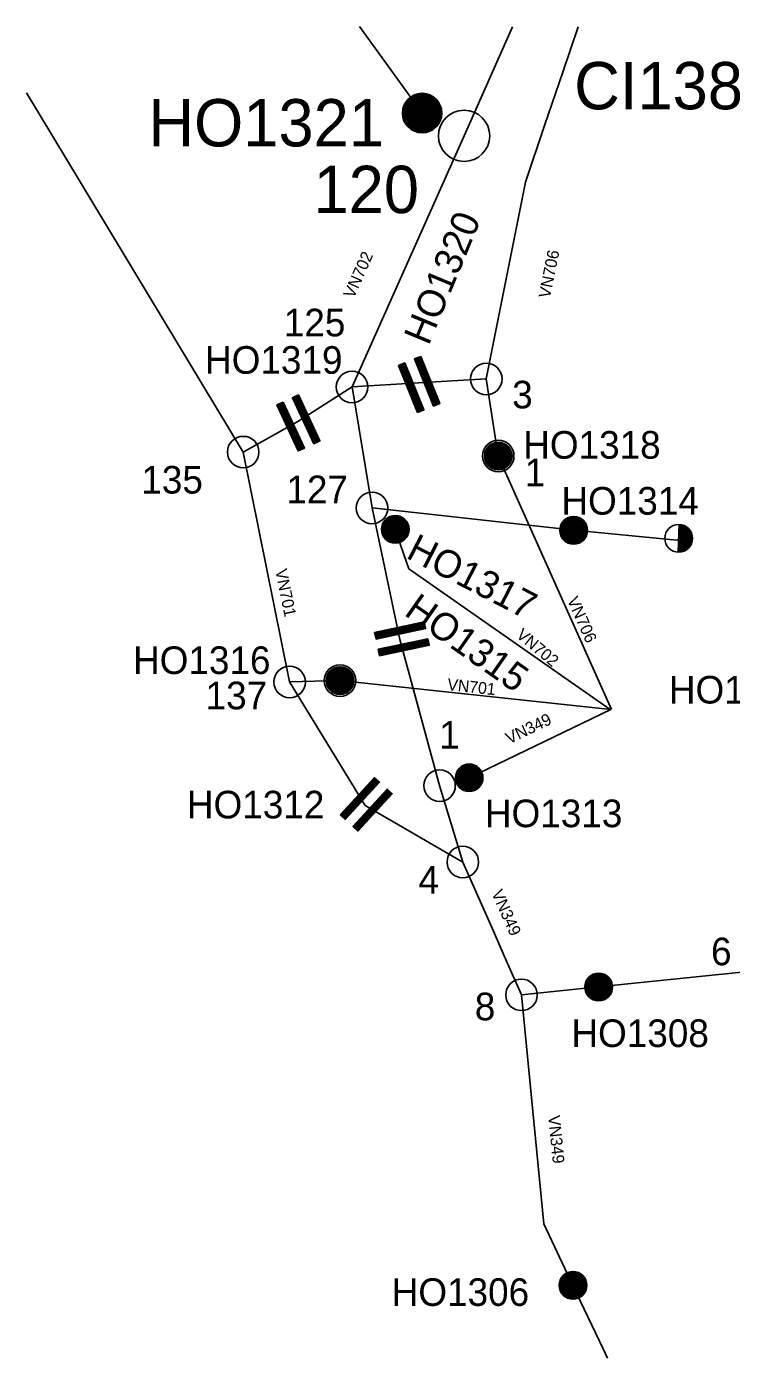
# Model space of a CAD drawing. Extents: x -536823 to -534989, y -1202231 to -1200421.
# Drawn here: x -536823 to -535929, y -1202141 to -1200454 of the extents above; entities that cross this region are included whole.
import ezdxf

# ---------------------------------------------------------------- set-up
doc = ezdxf.new("R2010")
doc.units = 0
for name, color, linetype in [('Default', 7, 'Continuous'), ('Vrstva 1', 7, 'Continuous'), ('Vrstva 2', 7, 'Continuous'), ('Vrstva 3', 7, 'Continuous'), ('Vrstva 5', 7, 'Continuous')]:
    doc.layers.add(name, color=color, linetype=linetype)

# ---------------------------------------------------------------- blocks, each defined once
blk = doc.blocks.new('PS100')
at = {"layer": 'Default'}
for p, q in [((-17.5, -0.7), (0.7, 17.5)), ((-17.5, 0.7), (-0.7, 17.5)), ((-17.4, -2), (2, 17.4)), ((-17.3, 2.2), (-2.2, 17.3)), ((-17.2, -3.3), (3.3, 17.2)), ((-17, 4), (-4, 17)), ((-16.9, -4.4), (4.4, 16.9)), ((-16.6, -5.5), (5.5, 16.6)), ((-16.4, 6), (-6, 16.4)), ((-16.2, -6.5), (6.5, 16.2)), ((-15.8, -7.5), (7.5, 15.8)), ((-15.3, -8.4), (8.4, 15.3)), ((-15.2, 8.6), (-8.6, 15.2)), ((-14.8, -9.3), (9.3, 14.8)), ((-14.2, -10.2), (10.2, 14.2)), ((-13.6, -11), (11, 13.6)), ((-13, -11.7), (11.7, 13)), ((-12.3, -12.5), (12.5, 12.3)), ((-11.5, -13.2), (13.2, 11.5)), ((-10.8, -13.8), (13.8, 10.8)), ((-9.9, -14.4), (14.4, 9.9)), ((-9.1, -14.9), (14.9, 9.1)), ((-8.2, -15.5), (15.5, 8.2)), ((-7.2, -15.9), (15.9, 7.2)), ((-6.2, -16.3), (16.3, 6.2)), ((-5.2, -16.7), (16.7, 5.2)), ((-4.1, -17), (17, 4.1)), ((-2.9, -17.2), (17.2, 2.9)), ((-1.6, -17.4), (17.4, 1.6)), ((-0.3, -17.5), (17.5, 0.3)), ((1.1, -17.4), (17.4, -1.1)), ((2.7, -17.3), (17.3, -2.7)), ((4.5, -16.9), (16.9, -4.5)), ((6.7, -16.2), (16.2, -6.7)), ((9.7, -14.5), (14.5, -9.7))]:
    blk.add_line(p, q, dxfattribs=at)
blk.add_circle((0, 0), 17.5, dxfattribs=at)
blk = doc.blocks.new('PS110')
at = {"layer": 'Default'}
for p, q in [((-15.1, 21.8), (-7.6, 29.3)), ((-15.1, 23.2), (-9.1, 29.3)), ((-15.1, 24.6), (-10.5, 29.3)), ((-15.1, 26), (-11.9, 29.3)), ((-15.1, 27.4), (-13.3, 29.3)), ((-15.1, 28.8), (-14.7, 29.3)), ((-15.1, 20.4), (-6.6, 28.9)), ((-15.1, 18.9), (-6.6, 27.5)), ((-15.1, 17.5), (-6.6, 26.1)), ((-15.1, 16.1), (-6.6, 24.7)), ((-15.1, 14.7), (-6.6, 23.3)), ((-15.1, 13.3), (-6.6, 21.8)), ((-15.1, 11.9), (-6.6, 20.4)), ((-15.1, 10.5), (-6.6, 19)), ((-15.1, 9), (-6.6, 17.6)), ((-6.6, -35), (-6.6, 29.3)), ((6.6, 20.7), (15.2, 29.3)), ((6.6, 22.1), (13.7, 29.3)), ((6.6, 23.5), (12.3, 29.3)), ((6.6, 24.9), (10.9, 29.3)), ((6.6, 26.4), (9.5, 29.3)), ((6.6, 27.8), (8.1, 29.3)), ((6.6, 29.2), (6.7, 29.3)), ((6.6, 19.3), (15.2, 27.8)), ((6.6, 17.9), (15.2, 26.4)), ((6.6, 16.5), (15.2, 25)), ((6.6, 15), (15.2, 23.6)), ((6.6, 13.6), (15.2, 22.2)), ((6.6, 12.2), (15.2, 20.8)), ((6.6, 10.8), (15.2, 19.4)), ((6.6, 9.4), (15.2, 18)), ((-15.1, 7.6), (-6.6, 16.2)), ((-15.1, 6.2), (-6.6, 14.8)), ((-15.1, 4.8), (-6.6, 13.4)), ((-15.1, 3.4), (-6.6, 11.9)), ((-15.1, 2), (-6.6, 10.5)), ((-15.1, 0.6), (-6.6, 9.1)), ((-15.1, -0.9), (-6.6, 7.7)), ((-15.1, -2.3), (-6.6, 6.3)), ((-15.1, -3.7), (-6.6, 4.9)), ((-15.1, -5.1), (-6.6, 3.5)), ((-15.1, -6.5), (-6.6, 2.1)), ((-15.1, -7.9), (-6.6, 0.6)), ((6.6, 8), (15.2, 16.5)), ((6.6, 6.6), (15.2, 15.1)), ((6.6, 5.1), (15.2, 13.7)), ((6.6, 3.7), (15.2, 12.3)), ((6.6, 2.3), (15.2, 10.9)), ((6.6, 0.9), (15.2, 9.5)), ((6.6, -0.5), (15.2, 8.1)), ((6.6, -1.9), (15.2, 6.6)), ((6.6, -3.3), (15.2, 5.2)), ((6.6, -4.8), (15.2, 3.8)), ((6.6, -6.2), (15.2, 2.4)), ((6.6, -7.6), (15.2, 1)), ((-15.1, -9.3), (-6.6, -0.8)), ((-15.1, -10.8), (-6.6, -2.2)), ((-15.1, -12.2), (-6.6, -3.6)), ((-15.1, -13.6), (-6.6, -5)), ((-15.1, -15), (-6.6, -6.4)), ((-15.1, -16.4), (-6.6, -7.8)), ((-15.1, -17.8), (-6.6, -9.3)), ((-15.1, -19.2), (-6.6, -10.7)), ((-15.1, -20.7), (-6.6, -12.1)), ((-15.1, -22.1), (-6.6, -13.5)), ((-15.1, -23.5), (-6.6, -14.9)), ((-15.1, -24.9), (-6.6, -16.3)), ((6.6, -9), (15.2, -0.4)), ((6.6, -10.4), (15.2, -1.8)), ((6.6, -11.8), (15.2, -3.3)), ((6.6, -13.2), (15.2, -4.7)), ((6.6, -14.7), (15.2, -6.1)), ((6.6, -16.1), (15.2, -7.5)), ((6.6, -17.5), (15.2, -8.9)), ((6.6, -18.9), (15.2, -10.3)), ((6.6, -20.3), (15.2, -11.7)), ((6.6, -21.7), (15.2, -13.2)), ((6.6, -23.1), (15.2, -14.6)), ((6.6, -24.6), (15.2, -16)), ((-15.1, -26.3), (-6.6, -17.7)), ((-15.1, -27.7), (-6.6, -19.2)), ((-15.1, -29.1), (-6.6, -20.6)), ((-15.1, -30.6), (-6.6, -22)), ((-15.1, -32), (-6.6, -23.4)), ((-15.1, -33.4), (-6.6, -24.8)), ((-15.1, -34.8), (-6.6, -26.2)), ((-13.9, -35), (-6.6, -27.6)), ((-12.5, -35), (-6.6, -29.1)), ((-11.1, -35), (-6.6, -30.5)), ((-9.6, -35), (-6.6, -31.9)), ((-8.2, -35), (-6.6, -33.3)), ((6.6, -26), (15.2, -17.4)), ((6.6, -27.4), (15.2, -18.8)), ((6.6, -28.8), (15.2, -20.2)), ((6.6, -30.2), (15.2, -21.6)), ((6.6, -31.6), (15.2, -23.1)), ((6.6, -33), (15.2, -24.5)), ((6.6, -34.5), (15.2, -25.9)), ((7.5, -35), (15.2, -27.3)), ((8.9, -35), (15.2, -28.7)), ((10.3, -35), (15.2, -30.1)), ((11.7, -35), (15.2, -31.5)), ((13.2, -35), (15.2, -33)), ((-6.8, -35), (-6.6, -34.7)), ((14.6, -35), (15.2, -34.4))]:
    blk.add_line(p, q, dxfattribs=at)
for points in [[(-6.6, 29.3), (-6.6, -35), (-15.1, -35), (-15.1, 29.3)], [(15.2, 29.3), (15.2, -35), (6.6, -35), (6.6, 29.3)]]:
    blk.add_lwpolyline(points, close=True, dxfattribs=at)
blk = doc.blocks.new('PS140')
at = {"layer": 'Default'}
for p, q in [((-17.5, 0), (0, 17.5)), ((-17.4, -1.4), (1.4, 17.4)), ((-17.4, 1.5), (-1.5, 17.4)), ((-17.3, -2.6), (2.6, 17.3)), ((-17.2, 3.1), (-3.1, 17.2)), ((-17.1, -3.8), (3.8, 17.1)), ((-16.8, -4.9), (4.9, 16.8)), ((-16.8, 5), (-5, 16.8)), ((-16.4, -6), (6, 16.4)), ((-16, -7), (7, 16)), ((-15.9, 7.2), (-7.2, 15.9)), ((-15.6, -8), (8, 15.6)), ((-15.1, -8.9), (8.9, 15.1)), ((-14.5, -9.8), (9.8, 14.5)), ((-13.9, -10.6), (10.6, 13.9)), ((-13.8, 10.8), (-10.8, 13.8)), ((-13.3, -11.4), (11.4, 13.3)), ((-12.6, -12.1), (12.1, 12.6)), ((-11.9, -12.8), (12.8, 11.9)), ((-11.2, -13.5), (13.5, 11.2)), ((-10.4, -14.1), (14.1, 10.4)), ((-9.5, -14.7), (14.7, 9.5)), ((-8.6, -15.2), (15.2, 8.6)), ((-7.7, -15.7), (15.7, 7.7)), ((-6.7, -16.1), (16.1, 6.7)), ((-5.7, -16.5), (16.5, 5.7)), ((-4.6, -16.9), (16.9, 4.6)), ((-3.5, -17.1), (17.1, 3.5)), ((-2.3, -17.3), (17.3, 2.3)), ((-1, -17.5), (17.5, 1)), ((0.4, -17.5), (17.5, -0.4)), ((1.9, -17.4), (17.4, -1.9)), ((3.6, -17.1), (17.1, -3.6)), ((5.5, -16.6), (16.6, -5.5)), ((8, -15.6), (15.6, -8))]:
    blk.add_line(p, q, dxfattribs=at)
blk.add_circle((0, 0), 17.5, dxfattribs=at)
blk = doc.blocks.new('PS150')
at = {"layer": 'Default'}
for p, q in [((-15.1, 22.4), (-7.4, 30.1)), ((-15.1, 23.8), (-8.8, 30.1)), ((-15.1, 25.2), (-10.2, 30.1)), ((-15.1, 26.6), (-11.6, 30.1)), ((-15.1, 28), (-13, 30.1)), ((-15.1, 29.4), (-14.4, 30.1)), ((-15.1, 20.9), (-6.5, 29.5)), ((-15.1, 19.5), (-6.5, 28.1)), ((-15.1, 18.1), (-6.5, 26.7)), ((-15.1, 16.7), (-6.5, 25.3)), ((-15.1, 15.3), (-6.5, 23.9)), ((-15.1, 13.9), (-6.5, 22.4)), ((-15.1, 12.5), (-6.5, 21)), ((-15.1, 11), (-6.5, 19.6)), ((-15.1, 9.6), (-6.5, 18.2)), ((6.7, 22.6), (14.1, 30.1)), ((6.7, 24), (12.7, 30.1)), ((6.7, 25.4), (11.3, 30.1)), ((6.7, 26.8), (9.9, 30.1)), ((6.7, 28.3), (8.5, 30.1)), ((6.7, 29.7), (7, 30.1)), ((6.7, 21.2), (15.2, 29.8)), ((6.7, 19.8), (15.2, 28.3)), ((6.7, 18.4), (15.2, 26.9)), ((6.7, 16.9), (15.2, 25.5)), ((6.7, 15.5), (15.2, 24.1)), ((6.7, 14.1), (15.2, 22.7)), ((6.7, 12.7), (15.2, 21.3)), ((6.7, 11.3), (15.2, 19.9)), ((6.7, 9.9), (15.2, 18.4)), ((6.7, 8.5), (15.2, 17)), ((-15.1, 8.2), (-6.5, 16.8)), ((-15.1, 6.8), (-6.5, 15.4)), ((-15.1, 5.4), (-6.5, 14)), ((-15.1, 4), (-6.5, 12.5)), ((-15.1, 2.6), (-6.5, 11.1)), ((-15.1, 1.2), (-6.5, 9.7)), ((-15.1, -0.3), (-6.5, 8.3)), ((-15.1, -1.7), (-6.5, 6.9)), ((-15.1, -3.1), (-6.5, 5.5)), ((-15.1, -4.5), (-6.5, 4.1)), ((-15.1, -5.9), (-6.5, 2.6)), ((-15.1, -7.3), (-6.5, 1.2)), ((6.7, 7.1), (15.2, 15.6)), ((6.7, 5.6), (15.2, 14.2)), ((6.7, 4.2), (15.2, 12.8)), ((6.7, 2.8), (15.2, 11.4)), ((6.7, 1.4), (15.2, 10)), ((6.7, 0), (15.2, 8.5)), ((6.7, -1.4), (15.2, 7.1)), ((6.7, -2.8), (15.2, 5.7)), ((6.7, -4.3), (15.2, 4.3)), ((6.7, -5.7), (15.2, 2.9)), ((6.7, -7.1), (15.2, 1.5)), ((6.7, -8.5), (15.2, 0.1)), ((-15.1, -8.7), (-6.5, -0.2)), ((-15.1, -10.2), (-6.5, -1.6)), ((-15.1, -11.6), (-6.5, -3)), ((-15.1, -13), (-6.5, -4.4)), ((-15.1, -14.4), (-6.5, -5.8)), ((-15.1, -15.8), (-6.5, -7.3)), ((-15.1, -17.2), (-6.5, -8.7)), ((-15.1, -18.6), (-6.5, -10.1)), ((-15.1, -20.1), (-6.5, -11.5)), ((-15.1, -21.5), (-6.5, -12.9)), ((-15.1, -22.9), (-6.5, -14.3)), ((-15.1, -24.3), (-6.5, -15.7)), ((6.7, -9.9), (15.2, -1.4)), ((6.7, -11.3), (15.2, -2.8)), ((6.7, -12.7), (15.2, -4.2)), ((6.7, -14.2), (15.2, -5.6)), ((6.7, -15.6), (15.2, -7)), ((6.7, -17), (15.2, -8.4)), ((6.7, -18.4), (15.2, -9.8)), ((6.7, -19.8), (15.2, -11.3)), ((6.7, -21.2), (15.2, -12.7)), ((6.7, -22.6), (15.2, -14.1)), ((6.7, -24.1), (15.2, -15.5)), ((-15.1, -25.7), (-6.5, -17.2)), ((-15.1, -27.1), (-6.5, -18.6)), ((-15.1, -28.5), (-6.5, -20)), ((-15.1, -30), (-6.5, -21.4)), ((-15.1, -31.4), (-6.5, -22.8)), ((-15.1, -32.8), (-6.5, -24.2)), ((-15, -34.2), (-6.5, -25.6)), ((-13.6, -34.2), (-6.5, -27.1)), ((-12.2, -34.2), (-6.5, -28.5)), ((-10.8, -34.2), (-6.5, -29.9)), ((-9.4, -34.2), (-6.5, -31.3)), ((-8, -34.2), (-6.5, -32.7)), ((6.7, -25.5), (15.2, -16.9)), ((6.7, -26.9), (15.2, -18.3)), ((6.7, -28.3), (15.2, -19.7)), ((6.7, -29.7), (15.2, -21.2)), ((6.7, -31.1), (15.2, -22.6)), ((6.7, -32.5), (15.2, -24)), ((6.7, -34), (15.2, -25.4)), ((7.9, -34.2), (15.2, -26.8)), ((9.3, -34.2), (15.2, -28.2)), ((10.7, -34.2), (15.2, -29.6)), ((12.1, -34.2), (15.2, -31)), ((13.5, -34.2), (15.2, -32.5)), ((-6.5, -34.2), (-6.5, -34.1)), ((14.9, -34.2), (15.2, -33.9))]:
    blk.add_line(p, q, dxfattribs=at)
for points in [[(-6.5, 30.1), (-6.5, -34.2), (-15.1, -34.2), (-15.1, 30.1)], [(15.2, 30.1), (15.2, -34.2), (6.7, -34.2), (6.7, 30.1)]]:
    blk.add_lwpolyline(points, close=True, dxfattribs=at)
blk = doc.blocks.new('PS400')
at = {"layer": 'Default'}
for p, q in [((-25, 0.1), (-0.1, 25)), ((-24.9, -1.2), (1.2, 24.9)), ((-24.9, 1.6), (-1.6, 24.9)), ((-24.8, -2.6), (2.6, 24.8)), ((-24.8, 3.2), (-3.2, 24.8)), ((-24.7, -3.8), (3.8, 24.7)), ((-24.5, -5), (5, 24.5)), ((-24.5, 4.9), (-4.9, 24.5)), ((-24.2, -6.2), (6.2, 24.2)), ((-24.1, 6.7), (-6.7, 24.1)), ((-23.9, -7.3), (7.3, 23.9)), ((-23.6, -8.3), (8.3, 23.6)), ((-23.4, 8.8), (-8.8, 23.4)), ((-23.2, -9.4), (9.4, 23.2)), ((-22.7, -10.3), (10.3, 22.7)), ((-22.3, -11.3), (11.3, 22.3)), ((-22.3, 11.3), (-11.3, 22.3)), ((-21.8, -12.2), (12.2, 21.8)), ((-21.3, -13.1), (13.1, 21.3)), ((-20.7, -14), (14, 20.7)), ((-20.1, -14.8), (14.8, 20.1)), ((-19.9, 15.2), (-15.2, 19.9)), ((-19.5, -15.6), (15.6, 19.5)), ((-18.9, -16.4), (16.4, 18.9)), ((-18.2, -17.1), (17.1, 18.2)), ((-17.5, -17.8), (17.8, 17.5)), ((-16.8, -18.5), (18.5, 16.8)), ((-16, -19.2), (19.2, 16)), ((-15.2, -19.8), (19.8, 15.2)), ((-14.4, -20.4), (20.4, 14.4)), ((-13.6, -21), (21, 13.6)), ((-12.7, -21.5), (21.5, 12.7)), ((-11.8, -22), (22, 11.8)), ((-10.8, -22.5), (22.5, 10.8)), ((-9.9, -22.9), (22.9, 9.9)), ((-8.9, -23.4), (23.4, 8.9)), ((-7.8, -23.7), (23.7, 7.8)), ((-6.7, -24.1), (24.1, 6.7)), ((-5.6, -24.3), (24.3, 5.6)), ((-4.4, -24.6), (24.6, 4.4)), ((-3.2, -24.8), (24.8, 3.2)), ((-1.9, -24.9), (24.9, 1.9)), ((-0.6, -25), (25, 0.6)), ((0.8, -25), (25, -0.8)), ((2.3, -24.9), (24.9, -2.3)), ((4, -24.7), (24.7, -4)), ((5.7, -24.3), (24.3, -5.7)), ((7.7, -23.8), (23.8, -7.7)), ((10, -22.9), (22.9, -10)), ((12.9, -21.4), (21.4, -12.9))]:
    blk.add_line(p, q, dxfattribs=at)
blk.add_circle((0, 0), 25, dxfattribs=at)
blk = doc.blocks.new('PS820')
at = {"layer": 'Vrstva 2'}
blk.add_circle((0, 0), 32.5, dxfattribs=at)
blk = doc.blocks.new('PS610')
at = {"layer": 'Default'}
for p, q in [((0, 16.2), (1.3, 17.4)), ((0, 14.7), (2.5, 17.3)), ((0, 13.3), (3.7, 17.1)), ((0, 11.9), (4.9, 16.8)), ((0, 10.5), (5.9, 16.4)), ((0, 9.1), (7, 16)), ((0, 7.7), (7.9, 15.6)), ((0, 6.3), (8.8, 15.1)), ((0, 4.8), (9.7, 14.5)), ((0, 3.4), (10.5, 14)), ((0, 2), (11.3, 13.3)), ((0, 0.6), (12, 12.7)), ((0, -0.8), (12.8, 12)), ((0, -2.2), (13.4, 11.2)), ((0, -3.6), (14, 10.4)), ((0, -5), (14.6, 9.6)), ((0, -6.5), (15.2, 8.7)), ((0, -7.9), (15.6, 7.8)), ((0, -9.3), (16.1, 6.8)), ((0, -10.7), (16.5, 5.8)), ((0, -12.1), (16.8, 4.7)), ((0, -13.5), (17.1, 3.6)), ((0, -14.9), (17.3, 2.4)), ((0, -16.4), (17.4, 1.1)), ((0.3, -17.5), (17.5, -0.3)), ((1.8, -17.4), (17.4, -1.8)), ((3.5, -17.1), (17.1, -3.5)), ((5.4, -16.7), (16.7, -5.4)), ((7.8, -15.7), (15.6, -7.8))]:
    blk.add_line(p, q, dxfattribs=at)
blk.add_lwpolyline([(0, 17.5), (0, -17.5)], dxfattribs=at)
blk.add_circle((0, 0), 17.5, dxfattribs=at)
blk = doc.blocks.new('PS800')
at = {"layer": 'Vrstva 2'}
blk.add_circle((0, 0), 20, dxfattribs=at)

msp = doc.modelspace()

# ---------------------------------------------------------------- linework, layer by layer
at = {"layer": 'Vrstva 1'}
for points in [[(-536321, -1200563), (-536400.4, -1200453.5)], [(-536206.4, -1200453.8), (-536267.8, -1200591.9)], [(-536239.7, -1200900), (-536189.8, -1200650.4), (-536165.6, -1200578.9), (-536142.6, -1200511.3), (-536123.2, -1200453.9)], [(-536822.5, -1200537.5), (-536547.9, -1200992.7)], [(-536267.8, -1200591.9), (-536267.8, -1200591.9), (-536409.8, -1200910.1), (-536409.8, -1200910.1)], [(-536478.8, -1200953.9), (-536409.8, -1200910.1)], [(-536409.8, -1200910.1), (-536325.6, -1200905.1)], [(-536409.8, -1200910.1), (-536384.5, -1201063.4)], [(-536325.6, -1200905.1), (-536239.7, -1200900)], [(-536224.5, -1200997.7), (-536239.7, -1200900)], [(-536547.9, -1200992.7), (-536478.8, -1200953.9)], [(-536547.9, -1200992.7), (-536489.1, -1201283.9)], [(-536081, -1201318.8), (-536224.5, -1200997.7)], [(-536384.5, -1201063.4), (-536128.8, -1201091.8)], [(-536384.5, -1201063.4), (-536349.4, -1201230)], [(-536082.5, -1201318.7), (-536337.9, -1201140.4), (-536355.1, -1201090.6)], [(-536128.8, -1201091.8), (-536128.8, -1201091.8), (-535997.9, -1201104.2), (-535995.7, -1201102)], [(-536349.4, -1201230), (-536298.9, -1201415.3)], [(-536489.1, -1201283.9), (-536425.2, -1201282.2)], [(-536081.5, -1201318.8), (-536425.2, -1201282.2)], [(-536489.1, -1201283.9), (-536393.2, -1201440.6)], [(-536081.7, -1201318.8), (-536261.3, -1201405.4)], [(-536298.9, -1201415.3), (-536269.4, -1201512.2)], [(-536393.2, -1201440.6), (-536393.2, -1201440.6), (-536269.4, -1201512.2)], [(-536269.4, -1201512.2), (-536250.8, -1201554.1), (-536232.3, -1201596.1), (-536213.8, -1201638), (-536195, -1201680.5)], [(-536097.1, -1201670.5), (-536047.7, -1201665.4), (-535998.2, -1201660.3), (-535948.8, -1201655.2), (-535898.8, -1201650.1)], [(-536195, -1201680.5), (-536195, -1201680.5), (-536146.5, -1201675.6), (-536097.1, -1201670.5)], [(-536195, -1201680.5), (-536181, -1201823.5), (-536166.6, -1201970.5), (-536129.7, -1202048.6)], [(-536129.7, -1202048.6), (-536129.7, -1202048.6), (-536091.6, -1202129.1), (-536085.9, -1202141.1)]]:
    msp.add_lwpolyline(points, dxfattribs=at)

# ---------------------------------------------------------------- block references
at = {"layer": 'Vrstva 2'}
for name, p, rotation in [('PS400', (-536321, -1200563), -54.68883858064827), ('PS150', (-536325.6, -1200905.1), 22.058347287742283), ('PS150', (-536478.8, -1200953.9), 24.930505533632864), ('PS100', (-536224.5, -1200997.7), -63.04782221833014), ('PS100', (-536355.1, -1201090.6), -34.51198329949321), ('PS140', (-536128.8, -1201091.8), -36.87871674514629), ('PS110', (-536349.4, -1201230), 101.92076800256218), ('PS100', (-536425.2, -1201282.2), -5.8432110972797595), ('PS100', (-536261.3, -1201405.4), -101.29804722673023), ('PS150', (-536393.2, -1201440.6), 137.4772422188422), ('PS140', (-536097.1, -1201670.5), 8.746161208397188), ('PS100', (-536129.7, -1202048.6), -64.68437496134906)]:
    msp.add_blockref(name, p, dxfattribs=dict(at, rotation=rotation))
at = {"layer": 'Vrstva 3', "rotation": -1.5327194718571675}
msp.add_blockref('PS610', (-535995.7, -1201102), dxfattribs=at)
at = {"layer": 'Vrstva 5'}
for name, p, rotation in [('PS820', (-536267.8, -1200591.9), 68.88273887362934), ('PS800', (-536239.7, -1200900), 22.062133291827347), ('PS800', (-536409.8, -1200910.1), 21.177100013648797), ('PS800', (-536547.9, -1200992.7), 22.397825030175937), ('PS800', (-536224.5, -1200997.7), -65.65072218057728), ('PS800', (-536384.5, -1201063.4), -58.203827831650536), ('PS800', (-536489.1, -1201283.9), 22.397825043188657), ('PS800', (-536425.2, -1201282.2), -67.60211944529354), ('PS800', (-536298.9, -1201415.3), 0.5631376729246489), ('PS800', (-536195, -1201680.5), 7.6230417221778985)]:
    msp.add_blockref(name, p, dxfattribs=dict(at, rotation=rotation))
msp.add_blockref('PS800', (-536269.4, -1201512.2), dxfattribs=at)

# ---------------------------------------------------------------- texts
at = {"layer": 'Vrstva 1'}
for s, rotation, p in [('VN702', 65.951, (-536407.7, -1200798.8)), ('VN706', 78.692, (-536158.8, -1200798.4)), ('VN701', 281.401, (-536507.3, -1201142.4)), ('VN706', 294.078, (-536137.5, -1201179.9)), ('VN702', 320.074, (-536202.7, -1201226.4)), ('VN701', 353.926, (-536289.6, -1201294.3)), ('VN349', 25.741, (-536210.6, -1201363.1)), ('VN349', 293.825, (-536233.4, -1201551.2)), ('VN349', 275.603, (-536161.2, -1201833.9))]:
    msp.add_text(s, height=15, rotation=rotation, dxfattribs=at).set_placement(p)
at = {"layer": 'Vrstva 2'}
for s, height, p in [('CI1384', 60, (-536128.2, -1200558.3)), ('HO1321', 60, (-536668.2, -1200605.3)), ('HO1319', 35, (-536596.3, -1200893.4)), ('HO1318', 35, (-536192.8, -1201001)), ('HO1314', 35, (-536144.4, -1201071.9)), ('HO1316', 35, (-536687.6, -1201273.9)), ('HO1311', 35, (-536008.1, -1201311.3)), ('HO1312', 35, (-536619.3, -1201456.9)), ('HO1313', 35, (-536241.4, -1201468)), ('HO1308', 35, (-536131.7, -1201746.6)), ('HO1306', 35, (-536359.6, -1202074.7))]:
    msp.add_text(s, height=height, dxfattribs=at).set_placement(p)
for s, rotation, p in [('HO1320', 67.485, (-536312.8, -1200858.7)), ('HO1317', 332.755, (-536342.8, -1201126.1)), ('HO1315', 324.904, (-536345.2, -1201198.4))]:
    msp.add_text(s, height=35, rotation=rotation, dxfattribs=at).set_placement(p)
at = {"layer": 'Vrstva 5'}
for s, height, p in [('120', 60, (-536458.8, -1200689.8)), ('125', 35, (-536496.4, -1200846)), ('3', 35, (-536206.8, -1200937.3)), ('135', 35, (-536677.1, -1201045.2)), ('1', 35, (-536190.9, -1201036)), ('127', 35, (-536493.1, -1201057.4)), ('137', 35, (-536595.6, -1201318.6)), ('1', 35, (-536299.3, -1201368.5)), ('4', 35, (-536325.7, -1201552.1)), ('6', 35, (-535954.6, -1201643)), ('8', 35, (-536254.2, -1201712.7))]:
    msp.add_text(s, height=height, dxfattribs=at).set_placement(p)

doc.saveas('drawing.dxf')
